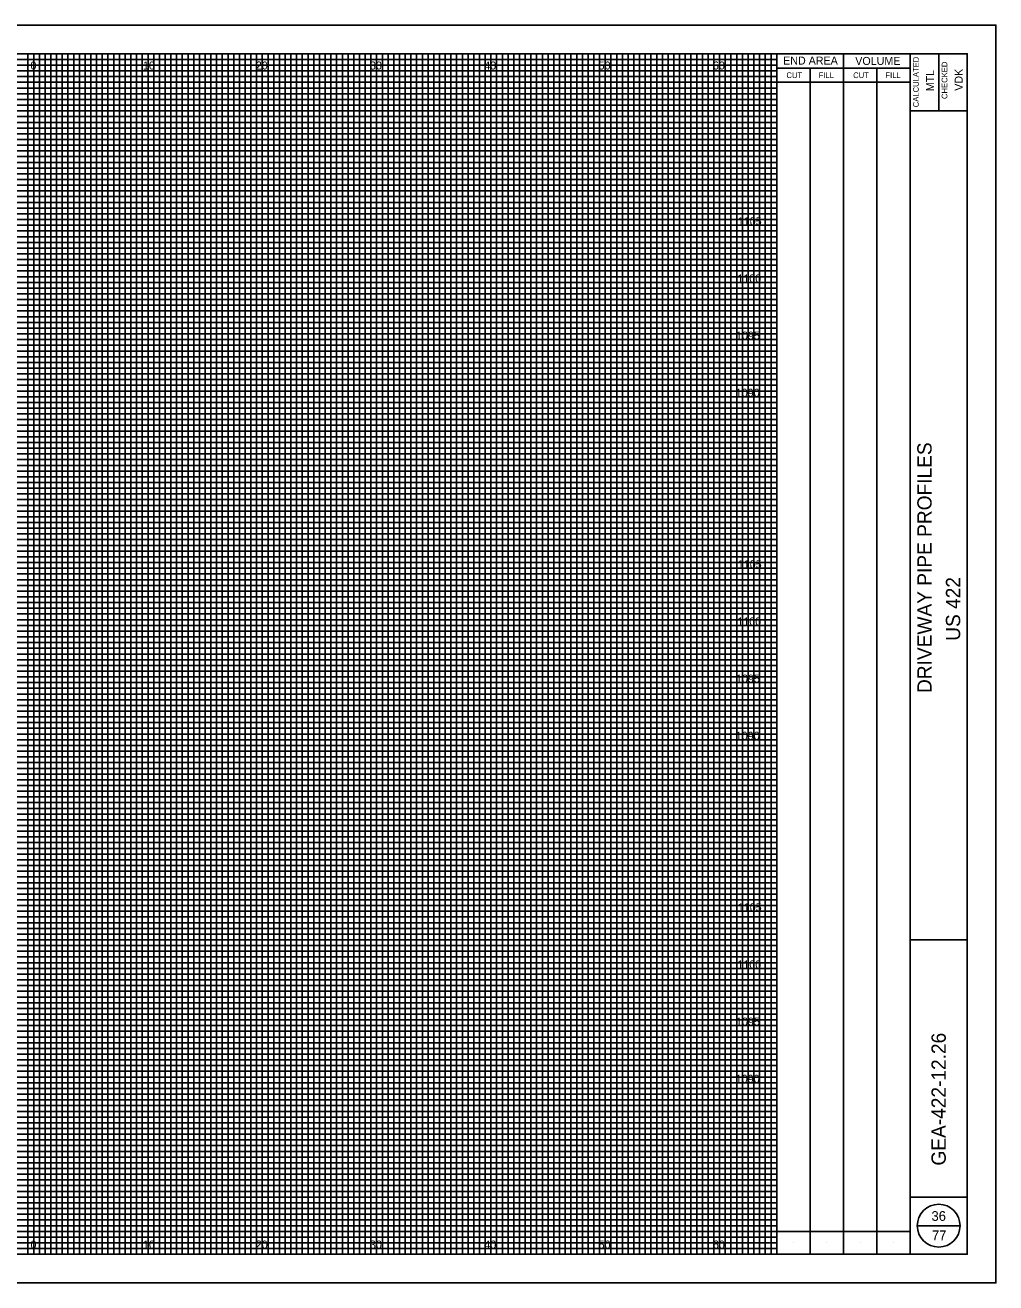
# Model space of a CAD drawing. Extents: x 0 to 170, y 0 to 110.
# Drawn here: x 85.1 to 170, y 0 to 110 of the extents above; entities that cross this region are included whole.
import ezdxf

# ---------------------------------------------------------------- set-up
doc = ezdxf.new("R2010")
doc.units = 0
for name, color, linetype in [('SH_Border', 7, 'Continuous'), ('SH_Cut_Line', 7, 'Continuous'), ('SH_Data', 7, 'Continuous'), ('SH_Major_Grid_Line', 7, 'Continuous'), ('SH_Minor_Grid_Line', 7, 'Continuous'), ('SH_Text', 7, 'Continuous')]:
    doc.layers.add(name, color=color, linetype=linetype)

msp = doc.modelspace()

# ---------------------------------------------------------------- linework, layer by layer
at = {"layer": 'SH_Border'}
for p, q in [((162.5, 2.5), (162.5, 107.5)), ((165, 107.5), (165, 102.5)), ((162.5, 102.5), (167.5, 102.5)), ((162.5, 30), (167.5, 30)), ((162.5, 7.5), (167.5, 7.5))]:
    msp.add_line(p, q, dxfattribs=at)
msp.add_lwpolyline([(10, 107.5), (167.5, 107.5), (167.5, 2.5), (10, 2.5)], close=True, dxfattribs=at)
at = {"layer": 'SH_Cut_Line'}
msp.add_lwpolyline([(0, 0), (170, 0), (170, 110), (0, 110)], close=True, dxfattribs=at)
at = {"layer": 'SH_Data'}
for p, q in [((150.83, 2.5), (150.83, 107.5)), ((156.67, 2.5), (156.67, 107.5)), ((150.83, 106.25), (162.5, 106.25)), ((153.75, 2.5), (153.75, 106.25)), ((159.58, 2.5), (159.58, 106.25)), ((150.83, 105), (162.5, 105)), ((150.83, 4.5), (162.5, 4.5)), ((163.12, 5), (166.88, 5)), ((152.29, 3.5), (152.29, 3.5)), ((155.21, 3.5), (155.21, 3.5)), ((158.12, 3.5), (158.12, 3.5)), ((161.04, 3.5), (161.04, 3.5))]:
    msp.add_line(p, q, dxfattribs=at)
msp.add_circle((165, 5), 1.87, dxfattribs=at)
at = {"layer": 'SH_Major_Grid_Line'}
for p, q in [((85.83, 2.5), (85.83, 107.5)), ((90.83, 2.5), (90.83, 107.5)), ((95.83, 2.5), (95.83, 107.5)), ((100.83, 2.5), (100.83, 107.5)), ((105.83, 2.5), (105.83, 107.5)), ((110.83, 2.5), (110.83, 107.5)), ((115.83, 2.5), (115.83, 107.5)), ((120.83, 2.5), (120.83, 107.5)), ((125.83, 2.5), (125.83, 107.5)), ((130.83, 2.5), (130.83, 107.5)), ((135.83, 2.5), (135.83, 107.5)), ((140.83, 2.5), (140.83, 107.5)), ((145.83, 2.5), (145.83, 107.5)), ((15.83, 102.5), (150.83, 102.5)), ((15.83, 97.5), (150.83, 97.5)), ((15.83, 92.5), (150.83, 92.5)), ((15.83, 87.5), (150.83, 87.5)), ((15.83, 82.5), (150.83, 82.5)), ((15.83, 77.5), (150.83, 77.5)), ((15.83, 72.5), (150.83, 72.5)), ((15.83, 67.5), (150.83, 67.5)), ((15.83, 62.5), (150.83, 62.5)), ((15.83, 57.5), (150.83, 57.5)), ((15.83, 52.5), (150.83, 52.5)), ((15.83, 47.5), (150.83, 47.5)), ((15.83, 42.5), (150.83, 42.5)), ((15.83, 37.5), (150.83, 37.5)), ((15.83, 32.5), (150.83, 32.5)), ((15.83, 27.5), (150.83, 27.5)), ((15.83, 22.5), (150.83, 22.5)), ((15.83, 17.5), (150.83, 17.5)), ((15.83, 12.5), (150.83, 12.5)), ((15.83, 7.5), (150.83, 7.5))]:
    msp.add_line(p, q, dxfattribs=at)
at = {"layer": 'SH_Minor_Grid_Line'}
for p, q in [((15.83, 107), (150.83, 107)), ((85.33, 2.5), (85.33, 107.5)), ((86.33, 2.5), (86.33, 107.5)), ((86.83, 2.5), (86.83, 107.5)), ((87.33, 2.5), (87.33, 107.5)), ((87.83, 2.5), (87.83, 107.5)), ((88.33, 2.5), (88.33, 107.5)), ((88.83, 2.5), (88.83, 107.5)), ((89.33, 2.5), (89.33, 107.5)), ((89.83, 2.5), (89.83, 107.5)), ((90.33, 2.5), (90.33, 107.5)), ((91.33, 2.5), (91.33, 107.5)), ((91.83, 2.5), (91.83, 107.5)), ((92.33, 2.5), (92.33, 107.5)), ((92.83, 2.5), (92.83, 107.5)), ((93.33, 2.5), (93.33, 107.5)), ((93.83, 2.5), (93.83, 107.5)), ((94.33, 2.5), (94.33, 107.5)), ((94.83, 2.5), (94.83, 107.5)), ((95.33, 2.5), (95.33, 107.5)), ((96.33, 2.5), (96.33, 107.5)), ((96.83, 2.5), (96.83, 107.5)), ((97.33, 2.5), (97.33, 107.5)), ((97.83, 2.5), (97.83, 107.5)), ((98.33, 2.5), (98.33, 107.5)), ((98.83, 2.5), (98.83, 107.5)), ((99.33, 2.5), (99.33, 107.5)), ((99.83, 2.5), (99.83, 107.5)), ((100.33, 2.5), (100.33, 107.5)), ((101.33, 2.5), (101.33, 107.5)), ((101.83, 2.5), (101.83, 107.5)), ((102.33, 2.5), (102.33, 107.5)), ((102.83, 2.5), (102.83, 107.5)), ((103.33, 2.5), (103.33, 107.5)), ((103.83, 2.5), (103.83, 107.5)), ((104.33, 2.5), (104.33, 107.5)), ((104.83, 2.5), (104.83, 107.5)), ((105.33, 2.5), (105.33, 107.5)), ((106.33, 2.5), (106.33, 107.5)), ((106.83, 2.5), (106.83, 107.5)), ((107.33, 2.5), (107.33, 107.5)), ((107.83, 2.5), (107.83, 107.5)), ((108.33, 2.5), (108.33, 107.5)), ((108.83, 2.5), (108.83, 107.5)), ((109.33, 2.5), (109.33, 107.5)), ((109.83, 2.5), (109.83, 107.5)), ((110.33, 2.5), (110.33, 107.5)), ((111.33, 2.5), (111.33, 107.5)), ((111.83, 2.5), (111.83, 107.5)), ((112.33, 2.5), (112.33, 107.5)), ((112.83, 2.5), (112.83, 107.5)), ((113.33, 2.5), (113.33, 107.5)), ((113.83, 2.5), (113.83, 107.5)), ((114.33, 2.5), (114.33, 107.5)), ((114.83, 2.5), (114.83, 107.5)), ((115.33, 2.5), (115.33, 107.5)), ((116.33, 2.5), (116.33, 107.5)), ((116.83, 2.5), (116.83, 107.5)), ((117.33, 2.5), (117.33, 107.5)), ((117.83, 2.5), (117.83, 107.5)), ((118.33, 2.5), (118.33, 107.5)), ((118.83, 2.5), (118.83, 107.5)), ((119.33, 2.5), (119.33, 107.5)), ((119.83, 2.5), (119.83, 107.5)), ((120.33, 2.5), (120.33, 107.5)), ((121.33, 2.5), (121.33, 107.5)), ((121.83, 2.5), (121.83, 107.5)), ((122.33, 2.5), (122.33, 107.5)), ((122.83, 2.5), (122.83, 107.5)), ((123.33, 2.5), (123.33, 107.5)), ((123.83, 2.5), (123.83, 107.5)), ((124.33, 2.5), (124.33, 107.5)), ((124.83, 2.5), (124.83, 107.5)), ((125.33, 2.5), (125.33, 107.5)), ((126.33, 2.5), (126.33, 107.5)), ((126.83, 2.5), (126.83, 107.5)), ((127.33, 2.5), (127.33, 107.5)), ((127.83, 2.5), (127.83, 107.5)), ((128.33, 2.5), (128.33, 107.5)), ((128.83, 2.5), (128.83, 107.5)), ((129.33, 2.5), (129.33, 107.5)), ((129.83, 2.5), (129.83, 107.5)), ((130.33, 2.5), (130.33, 107.5)), ((131.33, 2.5), (131.33, 107.5)), ((131.83, 2.5), (131.83, 107.5)), ((132.33, 2.5), (132.33, 107.5)), ((132.83, 2.5), (132.83, 107.5)), ((133.33, 2.5), (133.33, 107.5)), ((133.83, 2.5), (133.83, 107.5)), ((134.33, 2.5), (134.33, 107.5)), ((134.83, 2.5), (134.83, 107.5)), ((135.33, 2.5), (135.33, 107.5)), ((136.33, 2.5), (136.33, 107.5)), ((136.83, 2.5), (136.83, 107.5)), ((137.33, 2.5), (137.33, 107.5)), ((137.83, 2.5), (137.83, 107.5)), ((138.33, 2.5), (138.33, 107.5)), ((138.83, 2.5), (138.83, 107.5)), ((139.33, 2.5), (139.33, 107.5)), ((139.83, 2.5), (139.83, 107.5)), ((140.33, 2.5), (140.33, 107.5)), ((141.33, 2.5), (141.33, 107.5)), ((141.83, 2.5), (141.83, 107.5)), ((142.33, 2.5), (142.33, 107.5)), ((142.83, 2.5), (142.83, 107.5)), ((143.33, 2.5), (143.33, 107.5)), ((143.83, 2.5), (143.83, 107.5)), ((144.33, 2.5), (144.33, 107.5)), ((144.83, 2.5), (144.83, 107.5)), ((145.33, 2.5), (145.33, 107.5)), ((146.33, 2.5), (146.33, 107.5)), ((146.83, 2.5), (146.83, 107.5)), ((147.33, 2.5), (147.33, 107.5)), ((147.83, 2.5), (147.83, 107.5)), ((148.33, 2.5), (148.33, 107.5)), ((148.83, 2.5), (148.83, 107.5)), ((149.33, 2.5), (149.33, 107.5)), ((149.83, 2.5), (149.83, 107.5)), ((150.33, 2.5), (150.33, 107.5)), ((15.83, 106.5), (150.83, 106.5)), ((15.83, 106), (150.83, 106)), ((15.83, 105.5), (150.83, 105.5)), ((15.83, 105), (150.83, 105)), ((15.83, 104.5), (150.83, 104.5)), ((15.83, 104), (150.83, 104)), ((15.83, 103.5), (150.83, 103.5)), ((15.83, 103), (150.83, 103)), ((15.83, 102), (150.83, 102)), ((15.83, 101.5), (150.83, 101.5)), ((15.83, 101), (150.83, 101)), ((15.83, 100.5), (150.83, 100.5)), ((15.83, 100), (150.83, 100)), ((15.83, 99.5), (150.83, 99.5)), ((15.83, 99), (150.83, 99)), ((15.83, 98.5), (150.83, 98.5)), ((15.83, 98), (150.83, 98)), ((15.83, 97), (150.83, 97)), ((15.83, 96.5), (150.83, 96.5)), ((15.83, 96), (150.83, 96)), ((15.83, 95.5), (150.83, 95.5)), ((15.83, 95), (150.83, 95)), ((15.83, 94.5), (150.83, 94.5)), ((15.83, 94), (150.83, 94)), ((15.83, 93.5), (150.83, 93.5)), ((15.83, 93), (150.83, 93)), ((15.83, 92), (150.83, 92)), ((15.83, 91.5), (150.83, 91.5)), ((15.83, 91), (150.83, 91)), ((15.83, 90.5), (150.83, 90.5)), ((15.83, 90), (150.83, 90)), ((15.83, 89.5), (150.83, 89.5)), ((15.83, 89), (150.83, 89)), ((15.83, 88.5), (150.83, 88.5)), ((15.83, 88), (150.83, 88)), ((15.83, 87), (150.83, 87)), ((15.83, 86.5), (150.83, 86.5)), ((15.83, 86), (150.83, 86)), ((15.83, 85.5), (150.83, 85.5)), ((15.83, 85), (150.83, 85)), ((15.83, 84.5), (150.83, 84.5)), ((15.83, 84), (150.83, 84)), ((15.83, 83.5), (150.83, 83.5)), ((15.83, 83), (150.83, 83)), ((15.83, 82), (150.83, 82)), ((15.83, 81.5), (150.83, 81.5)), ((15.83, 81), (150.83, 81)), ((15.83, 80.5), (150.83, 80.5)), ((15.83, 80), (150.83, 80)), ((15.83, 79.5), (150.83, 79.5)), ((15.83, 79), (150.83, 79)), ((15.83, 78.5), (150.83, 78.5)), ((15.83, 78), (150.83, 78)), ((15.83, 77), (150.83, 77)), ((15.83, 76.5), (150.83, 76.5)), ((15.83, 76), (150.83, 76)), ((15.83, 75.5), (150.83, 75.5)), ((15.83, 75), (150.83, 75)), ((15.83, 74.5), (150.83, 74.5)), ((15.83, 74), (150.83, 74)), ((15.83, 73.5), (150.83, 73.5)), ((15.83, 73), (150.83, 73)), ((15.83, 72), (150.83, 72)), ((15.83, 71.5), (150.83, 71.5)), ((15.83, 71), (150.83, 71)), ((15.83, 70.5), (150.83, 70.5)), ((15.83, 70), (150.83, 70)), ((15.83, 69.5), (150.83, 69.5)), ((15.83, 69), (150.83, 69)), ((15.83, 68.5), (150.83, 68.5)), ((15.83, 68), (150.83, 68)), ((15.83, 67), (150.83, 67)), ((15.83, 66.5), (150.83, 66.5)), ((15.83, 66), (150.83, 66)), ((15.83, 65.5), (150.83, 65.5)), ((15.83, 65), (150.83, 65)), ((15.83, 64.5), (150.83, 64.5)), ((15.83, 64), (150.83, 64)), ((15.83, 63.5), (150.83, 63.5)), ((15.83, 63), (150.83, 63)), ((15.83, 62), (150.83, 62)), ((15.83, 61.5), (150.83, 61.5)), ((15.83, 61), (150.83, 61)), ((15.83, 60.5), (150.83, 60.5)), ((15.83, 60), (150.83, 60)), ((15.83, 59.5), (150.83, 59.5)), ((15.83, 59), (150.83, 59)), ((15.83, 58.5), (150.83, 58.5)), ((15.83, 58), (150.83, 58)), ((15.83, 57), (150.83, 57)), ((15.83, 56.5), (150.83, 56.5)), ((15.83, 56), (150.83, 56)), ((15.83, 55.5), (150.83, 55.5)), ((15.83, 55), (150.83, 55)), ((15.83, 54.5), (150.83, 54.5)), ((15.83, 54), (150.83, 54)), ((15.83, 53.5), (150.83, 53.5)), ((15.83, 53), (150.83, 53)), ((15.83, 52), (150.83, 52)), ((15.83, 51.5), (150.83, 51.5)), ((15.83, 51), (150.83, 51)), ((15.83, 50.5), (150.83, 50.5)), ((15.83, 50), (150.83, 50)), ((15.83, 49.5), (150.83, 49.5)), ((15.83, 49), (150.83, 49)), ((15.83, 48.5), (150.83, 48.5)), ((15.83, 48), (150.83, 48)), ((15.83, 47), (150.83, 47)), ((15.83, 46.5), (150.83, 46.5)), ((15.83, 46), (150.83, 46)), ((15.83, 45.5), (150.83, 45.5)), ((15.83, 45), (150.83, 45)), ((15.83, 44.5), (150.83, 44.5)), ((15.83, 44), (150.83, 44)), ((15.83, 43.5), (150.83, 43.5)), ((15.83, 43), (150.83, 43)), ((15.83, 42), (150.83, 42)), ((15.83, 41.5), (150.83, 41.5)), ((15.83, 41), (150.83, 41)), ((15.83, 40.5), (150.83, 40.5)), ((15.83, 40), (150.83, 40)), ((15.83, 39.5), (150.83, 39.5)), ((15.83, 39), (150.83, 39)), ((15.83, 38.5), (150.83, 38.5)), ((15.83, 38), (150.83, 38)), ((15.83, 37), (150.83, 37)), ((15.83, 36.5), (150.83, 36.5)), ((15.83, 36), (150.83, 36)), ((15.83, 35.5), (150.83, 35.5)), ((15.83, 35), (150.83, 35)), ((15.83, 34.5), (150.83, 34.5)), ((15.83, 34), (150.83, 34)), ((15.83, 33.5), (150.83, 33.5)), ((15.83, 33), (150.83, 33)), ((15.83, 32), (150.83, 32)), ((15.83, 31.5), (150.83, 31.5)), ((15.83, 31), (150.83, 31)), ((15.83, 30.5), (150.83, 30.5)), ((15.83, 30), (150.83, 30)), ((15.83, 29.5), (150.83, 29.5)), ((15.83, 29), (150.83, 29)), ((15.83, 28.5), (150.83, 28.5)), ((15.83, 28), (150.83, 28)), ((15.83, 27), (150.83, 27)), ((15.83, 26.5), (150.83, 26.5)), ((15.83, 26), (150.83, 26)), ((15.83, 25.5), (150.83, 25.5)), ((15.83, 25), (150.83, 25)), ((15.83, 24.5), (150.83, 24.5)), ((15.83, 24), (150.83, 24)), ((15.83, 23.5), (150.83, 23.5)), ((15.83, 23), (150.83, 23)), ((15.83, 22), (150.83, 22)), ((15.83, 21.5), (150.83, 21.5)), ((15.83, 21), (150.83, 21)), ((15.83, 20.5), (150.83, 20.5)), ((15.83, 20), (150.83, 20)), ((15.83, 19.5), (150.83, 19.5)), ((15.83, 19), (150.83, 19)), ((15.83, 18.5), (150.83, 18.5)), ((15.83, 18), (150.83, 18)), ((15.83, 17), (150.83, 17)), ((15.83, 16.5), (150.83, 16.5)), ((15.83, 16), (150.83, 16)), ((15.83, 15.5), (150.83, 15.5)), ((15.83, 15), (150.83, 15)), ((15.83, 14.5), (150.83, 14.5)), ((15.83, 14), (150.83, 14)), ((15.83, 13.5), (150.83, 13.5)), ((15.83, 13), (150.83, 13)), ((15.83, 12), (150.83, 12)), ((15.83, 11.5), (150.83, 11.5)), ((15.83, 11), (150.83, 11)), ((15.83, 10.5), (150.83, 10.5)), ((15.83, 10), (150.83, 10)), ((15.83, 9.5), (150.83, 9.5)), ((15.83, 9), (150.83, 9)), ((15.83, 8.5), (150.83, 8.5)), ((15.83, 8), (150.83, 8)), ((15.83, 7), (150.83, 7)), ((15.83, 6.5), (150.83, 6.5)), ((15.83, 6), (150.83, 6)), ((15.83, 5.5), (150.83, 5.5)), ((15.83, 5), (150.83, 5)), ((15.83, 4.5), (150.83, 4.5)), ((15.83, 4), (150.83, 4)), ((15.83, 3.5), (150.83, 3.5)), ((15.83, 3), (150.83, 3))]:
    msp.add_line(p, q, dxfattribs=at)

# ---------------------------------------------------------------- texts
at = {"layer": 'SH_Data'}
for s, height, p in [('END AREA', 0.7, (151.39, 106.55)), ('VOLUME', 0.7, (157.7, 106.52)), ('CUT', 0.5, (151.68, 105.37)), ('FILL', 0.5, (154.5, 105.37)), ('CUT', 0.5, (157.52, 105.37)), ('FILL', 0.5, (160.34, 105.37)), ('36', 0.85, (164.37, 5.42)), ('77', 0.85, (164.41, 3.73))]:
    msp.add_text(s, height=height, dxfattribs=at).set_placement(p)
for s, height, p in [('CALCULATED', 0.5, (163.26, 102.82)), ('CHECKED', 0.5, (165.76, 103.54)), ('MTL', 0.7, (164.6, 104.22)), ('VDK', 0.7, (167.1, 104.26)), ('DRIVEWAY PIPE PROFILES', 1.25, (164.38, 51.59)), ('        US 422        ', 1.25, (166.88, 52.44)), (' GEA-422-12.26 ', 1.25, (165.62, 9.79))]:
    msp.add_text(s, height=height, rotation=90, dxfattribs=at).set_placement(p)
at = {"layer": 'SH_Text'}
for s, p in [('0', (85.55, 106.12)), ('0', (85.55, 106.12)), ('10', (95.39, 106.12)), ('20', (105.26, 106.12)), ('30', (115.25, 106.12)), ('40', (125.25, 106.12)), ('50', (135.25, 106.12)), ('60', (145.25, 106.12)), ('1105', (147.43, 92.5)), ('1100', (147.39, 87.5)), ('1095', (147.27, 82.5)), ('1090', (147.25, 77.5)), ('1105', (147.43, 62.5)), ('1100', (147.39, 57.5)), ('1095', (147.27, 52.5)), ('1090', (147.25, 47.5)), ('1105', (147.43, 32.5)), ('1100', (147.39, 27.5)), ('1095', (147.27, 22.5)), ('1090', (147.25, 17.5)), ('0', (85.55, 3)), ('0', (85.55, 3)), ('10', (95.39, 3)), ('20', (105.26, 3)), ('30', (115.25, 3)), ('40', (125.25, 3)), ('50', (135.25, 3)), ('60', (145.25, 3))]:
    msp.add_text(s, height=0.7, dxfattribs=at).set_placement(p)

doc.saveas('drawing.dxf')
